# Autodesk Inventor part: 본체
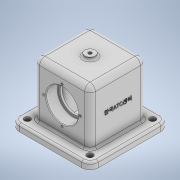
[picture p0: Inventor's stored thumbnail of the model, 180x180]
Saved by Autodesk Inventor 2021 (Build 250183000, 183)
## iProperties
Created: 2022-07
Part Number: 본체
Material: 일반
Document SubType Name: Modeling
Designer: i
Density: 1 g/cm^3
Appearance: 기본값
Author: i
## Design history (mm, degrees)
sketch "스케치1"
  geometry: L1 (-58, 58)-(58, 58); L2 (58, 58)-(58, -58); L3 (58, -58)-(-58, -58); L4 (-58, -58)-(-58, 58); L5 (-58, 58)-(58, -58); L6 (58, 58)-(-58, -58); 1 further point
  constraints: 12 end point, 2 midpoint, 2 parallel, 1 horizontal, 1 perpendicular
  dimensions: "d0" = 116 distance of L1.end L2.end; "d1" = 116 distance of L2.end L3.end
extrude "돌출1" new body sketch "스케치1" distance "d2" = 10; taper "d3" = 0 deg
sketch "스케치2"
  geometry: L1 (-41, -41)-(41, -41); L2 (41, -41)-(41, 41); L3 (41, 41)-(-41, 41); L4 (-41, 41)-(-41, -41); L5 (-41, -41)-(41, 41); L6 (41, -41)-(-41, 41); 1 further point
  constraints: 12 end point, 2 midpoint, 2 parallel, 1 horizontal, 1 perpendicular
  dimensions: "d4" = 82 distance of L3.end L1.start; "d5" = 82 distance of L2.end L3.end
extrude "돌출2" join sketch "스케치2" distance "d6" = 80; taper "d7" = 0 deg
sketch "스케치3"
  geometry: C1 r 7.5 at (0, 0); 1 further point
  constraints: 1 centre point, 1 coincident
  dimensions: "d8" = 15 diameter of C1
extrude "돌출3" join sketch "스케치3" distance "d9" = 4; taper "d10" = 0 deg
sketch "스케치4"
  geometry: L1 (-30, 21)-(30, 21); L2 (30, 21)-(30, -21); L3 (30, -21)-(-30, -21); L4 (-30, -21)-(-30, 21); L5 (-30, 21)-(30, -21); L6 (30, 21)-(-30, -21); C1 r 7.5 at (0, 0) reference; 1 further point
  constraints: 12 end point, 2 midpoint, 2 parallel, 1 horizontal, 1 perpendicular
  dimensions: "d11" = 42 distance of L1.end L2.end; "d12" = 60 distance of L2.end L3.end
extrude "돌출4" cut sketch "스케치4" distance "d13" = 80; taper "d14" = 0 deg
sketch "스케치5"
  geometry: L1 (41, -10)-(41, 38); L2 (82, 0)-(82, 80) reference; L3 (0, 0)-(0, 80) reference
  constraints: 2 end point, 1 vertical
  dimensions: "d15" = 48 distance of L1.start L1.end; "d16" = 41 distance between parallel lines of L2 L1 (derived); "d17" = 41 distance between parallel lines of L1 L3 (derived)
hole "구멍1" sketch "스케치5" at (41, 38) diameter "d18" = 47; stored, may be unused: countersink angle "d22" = 90 deg, drill point angle "d24" = 0 deg; dims "d19" = 8, "d20" = 4, "d21" = 2, "d23" = 17
sketch "스케치6"
  geometry: C1 r 23.5 at (0, 0) reference; 2 further points
  constraints: 1 coincident
hole "구멍2" sketch "스케치6" at (0, 0) diameter "d25" = 40; stored, may be unused: countersink angle "d29" = 90 deg, drill point angle "d31" = 0 deg; dims "d26" = 8, "d27" = 4, "d28" = 2, "d30" = 17
sketch "스케치7"
  geometry: C1 r 7.5 at (0, 0) reference; 2 further points
  constraints: 1 coincident
hole "구멍3" sketch "스케치7" at (0, 0) diameter "d32" = 4.917; stored, may be unused: countersink angle "d36" = 90 deg, drill point angle "d38" = 0 deg; dims "d33" = 80, "d34" = 4, "d35" = 2, "d37" = 17
sketch "스케치8"
  geometry: L1 (41, 38)-(41, 65); C1 r 23.5 at (41, 38) reference; 1 further point
  constraints: 2 end point, 1 vertical
  dimensions: "d39" = 27 distance of L1.start L1.end
hole "구멍4" sketch "스케치8" at (41, 65) diameter "d40" = 3.242; stored, may be unused: countersink angle "d44" = 90 deg, drill point angle "d46" = 118 deg; dims "d41" = 8, "d42" = 4, "d43" = 2, "d45" = 10
fillet "모깎기1" dims "d50" = 12
sketch "스케치9"
  geometry: A1 r 12 centre (46, -46) between (46, -58) and (58, -46) reference; A2 r 12 centre (46, 46) between (58, 46) and (46, 58) reference; A3 r 12 centre (-46, -46) between (-58, -46) and (-46, -58) reference; A4 r 12 centre (-46, 46) between (-46, 58) and (-58, 46) reference; 5 further points
  constraints: 4 coincident
hole "구멍5" sketch "스케치9" at (46, -46), (46, 46), (-46, -46), (-46, 46) diameter "d51" = 9; stored, may be unused: countersink angle "d55" = 90 deg, drill point angle "d57" = 118 deg; dims "d52" = 8, "d53" = 4, "d54" = 2, "d56" = 10
sketch "스케치10"
  geometry: L1 (48.5, 84)-(33.5, 84) reference; L2 (-5, -10)-(87, -10) reference; L3 (0, 0)-(0, 80) reference; L4 (82, 0)-(82, 80) reference; 2 further points
  constraints: 1 other
  dimensions: "d58" = 48 distance from line of L2 point (41, 38); "d59" = 41 distance from line of L3 point (41, 38) (= d60); "d60" = 41 distance from line of L4 point (41, 38) (derived)
feature "엠보싱1" sketch "스케치10" dims "d0" = 116, "d1" = 116, "d61" = 0.5, "d62" = 0
fillet "모깎기2" dims "d63" = 8
fillet "모깎기3" dims "d64" = 8
chamfer "모따기1" distance "d65" = 1; stored, may be unused: second distance "d66" = 2, angle "d67" = 45 deg
fillet "모깎기4" dims "d68" = 0.6
fillet "모깎기5" dims "d69" = 3
fillet "모깎기6" dims "d70" = 3
fillet "모깎기7" dims "d71" = 3
fillet "모깎기8" dims "d72" = 3
node "솔리드1"
mirror "미러1"
pattern_circular "원형 패턴1" dims angle "d48" = 360 deg
mirror "미러2"
feature "A9D066F2-1C7D-4E18-AEED-F7BC21143FA4" dims "d18" = 47, "d19" = 8, "d20" = 4, "d21" = 2, "d22" = 90 deg, "d23" = 17, "d24" = 0
